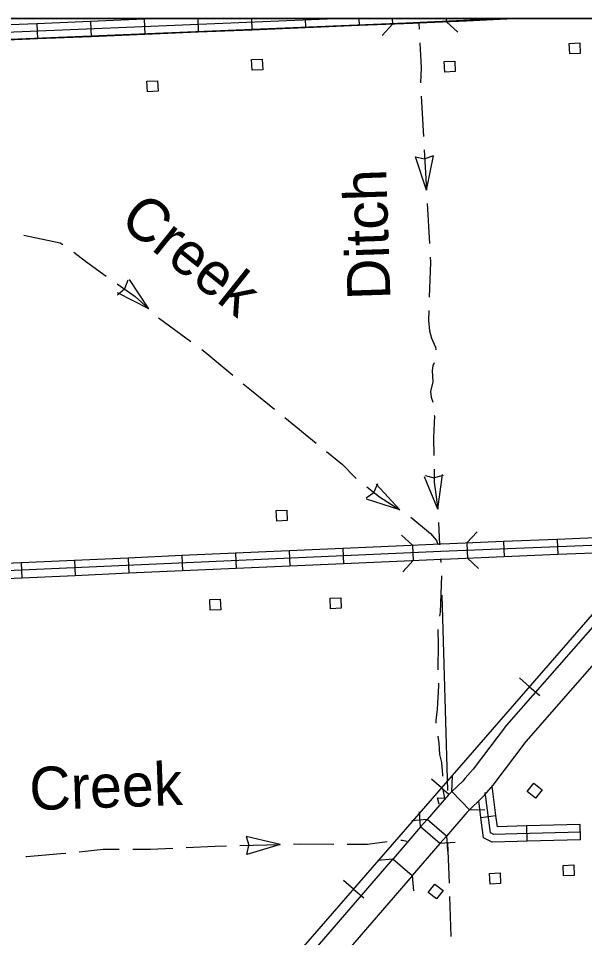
# Model space of a CAD drawing. Extents: x -0.3 to 2.65, y 0 to 1.9.
# Drawn here: x 0.579 to 0.6457, y 0.4334 to 0.5417 of the extents above; entities that cross this region are included whole.
import ezdxf

# ---------------------------------------------------------------- set-up
doc = ezdxf.new("R2010")
doc.units = 0
for name, color, linetype in [('DSN_DRFT_DNC', 7, 'Continuous'), ('Level 12', 7, 'Continuous'), ('Level 15', 7, 'Continuous'), ('Level 19', 7, 'Continuous'), ('Level 20', 7, 'Continuous'), ('Level 27', 7, 'Continuous'), ('Level 28', 7, 'Continuous'), ('Level 29', 7, 'Continuous'), ('Level 30', 7, 'Continuous'), ('Level 6', 7, 'Continuous')]:
    doc.layers.add(name, color=color, linetype=linetype)

msp = doc.modelspace()

# ---------------------------------------------------------------- linework, layer by layer
at = {"layer": 'DSN_DRFT_DNC'}
msp.add_lwpolyline([(0.38477, 0.54167), (1.0319, 0.54167), (1.0319, 0.1443), (0.38477, 0.1443)], close=True, dxfattribs=at)
at = {"layer": 'Level 12'}
for p, q in [((0.62576, 0.52535), (0.62683, 0.52513)), ((0.62704, 0.52145), (0.62576, 0.52535)), ((0.62788, 0.52547), (0.62684, 0.52513)), ((0.62704, 0.52145), (0.62788, 0.52547)), ((0.59188, 0.51083), (0.5915, 0.50981)), ((0.59434, 0.50747), (0.5921, 0.51092)), ((0.59065, 0.5091), (0.59149, 0.5098)), ((0.59434, 0.50747), (0.59068, 0.50934)), ((0.62837, 0.48389), (0.62681, 0.48769)), ((0.62691, 0.48784), (0.62796, 0.48755)), ((0.62903, 0.48783), (0.62797, 0.48755)), ((0.62837, 0.48389), (0.62892, 0.48796)), ((0.62128, 0.48687), (0.62085, 0.48586)), ((0.6239, 0.48381), (0.62112, 0.48683)), ((0.61996, 0.4852), (0.62084, 0.48585)), ((0.6239, 0.48381), (0.61998, 0.48504)), ((0.62833, 0.44989), (0.62917, 0.44983)), ((0.62855, 0.44914), (0.62833, 0.44987)), ((0.60583, 0.44534), (0.60614, 0.44429)), ((0.60982, 0.44439), (0.60583, 0.44534)), ((0.60982, 0.44439), (0.60589, 0.44322)), ((0.60589, 0.44322), (0.60614, 0.44428))]:
    msp.add_line(p, q, dxfattribs=at)
for points in [[(0.62614, 0.54109), (0.62617, 0.54038)], [(0.62626, 0.5388), (0.62642, 0.53586), (0.62635, 0.53407)], [(0.62643, 0.53249), (0.62669, 0.52776)], [(0.62678, 0.52618), (0.62704, 0.52145)], [(0.62713, 0.51987), (0.62739, 0.51514)], [(0.57965, 0.51615), (0.58392, 0.51522), (0.58423, 0.51503)], [(0.58554, 0.51415), (0.5869, 0.51308), (0.58935, 0.51133)], [(0.62748, 0.51356), (0.62751, 0.51295), (0.62738, 0.50883)], [(0.59063, 0.51041), (0.59273, 0.50892), (0.59434, 0.50747)], [(0.62733, 0.50725), (0.6273, 0.50613), (0.62739, 0.50489), (0.62765, 0.50401), (0.62811, 0.50296), (0.62814, 0.50265)], [(0.59551, 0.50641), (0.59561, 0.50632), (0.59932, 0.5036)], [(0.6006, 0.50266), (0.60094, 0.50241), (0.60426, 0.49965)], [(0.62797, 0.50111), (0.62781, 0.50077), (0.6277, 0.50019), (0.62778, 0.49886), (0.62752, 0.49772), (0.62761, 0.49708), (0.62778, 0.49648)], [(0.60547, 0.49865), (0.60643, 0.49785), (0.60914, 0.49564)], [(0.62797, 0.49492), (0.62798, 0.49486), (0.62787, 0.49226), (0.62793, 0.49018)], [(0.61036, 0.49465), (0.61404, 0.49166)], [(0.61526, 0.49066), (0.61716, 0.48912), (0.6186, 0.48763), (0.61878, 0.48749)], [(0.62797, 0.4886), (0.62796, 0.48704), (0.62837, 0.48389)], [(0.62002, 0.48651), (0.6215, 0.48533), (0.6239, 0.48381)], [(0.6252, 0.48292), (0.62752, 0.48102), (0.62823, 0.48017), (0.6284, 0.47973)], [(0.62848, 0.48232), (0.62858, 0.47969)], [(0.62868, 0.47801), (0.62872, 0.47759)], [(0.62881, 0.47601), (0.62864, 0.47175), (0.62859, 0.47128)], [(0.6284, 0.46971), (0.62837, 0.46946), (0.62842, 0.4681), (0.6284, 0.46497)], [(0.62846, 0.4634), (0.62847, 0.46305), (0.62829, 0.46034), (0.62814, 0.459), (0.62813, 0.45867)], [(0.62839, 0.45713), (0.62852, 0.45631), (0.62859, 0.455), (0.62881, 0.45404), (0.62895, 0.45258), (0.62895, 0.45244)], [(0.62898, 0.45087), (0.62918, 0.44981)], [(0.58616, 0.44354), (0.589, 0.44382), (0.59088, 0.44382)], [(0.59246, 0.44382), (0.59457, 0.44382), (0.5972, 0.44394)], [(0.59877, 0.44402), (0.60218, 0.44418), (0.60351, 0.44421)], [(0.60509, 0.44426), (0.60982, 0.44439)], [(0.6114, 0.44443), (0.61213, 0.44445), (0.61614, 0.44443)], [(0.61772, 0.44442), (0.62011, 0.44441), (0.62243, 0.44475)], [(0.62401, 0.44488), (0.62422, 0.44488), (0.62472, 0.44476)], [(0.62953, 0.44459), (0.6297, 0.43985)], [(0.57986, 0.44299), (0.57998, 0.44299), (0.58396, 0.44331), (0.58459, 0.44338)], [(0.62976, 0.43828), (0.62993, 0.43354)]]:
    msp.add_lwpolyline(points, dxfattribs=at)
at = {"layer": 'Level 15'}
for p, q in [((0.58748, 0.5413), (0.58756, 0.53951)), ((0.59582, 0.54164), (0.5938, 0.54156)), ((0.5938, 0.54156), (0.59387, 0.53977)), ((0.60012, 0.54164), (0.60018, 0.54003)), ((0.60644, 0.54164), (0.6065, 0.54029)), ((0.61276, 0.54164), (0.61281, 0.54055)), ((0.61909, 0.54164), (0.61912, 0.54081)), ((0.62302, 0.54164), (0.62305, 0.54097)), ((0.62937, 0.54164), (0.62939, 0.54123)), ((0.63222, 0.54164), (0.63223, 0.54138)), ((0.63811, 0.54164), (0.63806, 0.54164)), ((0.63806, 0.54164), (0.63806, 0.54164)), ((0.58117, 0.54104), (0.58125, 0.53925)), ((0.62541, 0.47961), (0.62548, 0.47782)), ((0.63179, 0.47987), (0.63186, 0.47808)), ((0.63612, 0.48005), (0.63619, 0.47826)), ((0.64243, 0.48031), (0.64251, 0.47852)), ((0.60456, 0.47868), (0.60464, 0.47688)), ((0.61087, 0.47896), (0.61095, 0.47716)), ((0.61718, 0.47924), (0.61726, 0.47744)), ((0.57931, 0.47755), (0.57939, 0.47576)), ((0.58562, 0.47784), (0.5857, 0.47604)), ((0.59193, 0.47812), (0.59201, 0.47632)), ((0.59825, 0.4784), (0.59832, 0.4766)), ((0.63345, 0.44757), (0.63523, 0.4478)), ((0.63892, 0.44478), (0.63888, 0.44658)), ((0.6452, 0.44495), (0.64516, 0.44674))]:
    msp.add_line(p, q, dxfattribs=at)
for points in [[(0.63649, 0.54164), (0.62462, 0.5411), (0.56089, 0.53848), (0.51348, 0.53639), (0.49209, 0.5356)], [(0.61723, 0.54164), (0.56237, 0.53938), (0.51495, 0.5373), (0.49357, 0.53651)], [(0.58748, 0.5413), (0.58117, 0.54104)], [(0.5938, 0.54156), (0.58748, 0.5413)], [(0.63175, 0.54135), (0.62614, 0.5411), (0.62544, 0.54107)], [(0.63806, 0.54164), (0.63175, 0.54135)], [(0.58117, 0.54104), (0.57486, 0.54078)], [(0.6065, 0.54029), (0.60018, 0.54003)], [(0.61281, 0.54055), (0.6065, 0.54029)], [(0.61912, 0.54081), (0.61281, 0.54055)], [(0.62544, 0.54107), (0.61912, 0.54081)], [(0.58125, 0.53925), (0.57493, 0.53899)], [(0.58756, 0.53951), (0.58125, 0.53925)], [(0.59387, 0.53977), (0.58756, 0.53951)], [(0.60018, 0.54003), (0.59387, 0.53977)], [(0.65507, 0.47962), (0.65429, 0.47984), (0.65142, 0.4798), (0.62875, 0.47887), (0.56702, 0.47613), (0.56558, 0.47592), (0.56498, 0.47581), (0.56493, 0.47458), (0.56546, 0.45822), (0.56606, 0.43494), (0.56734, 0.41056)], [(0.62981, 0.47979), (0.62871, 0.47975), (0.62349, 0.47952)], [(0.63612, 0.48005), (0.62981, 0.47979)], [(0.64243, 0.48031), (0.63612, 0.48005)], [(0.64875, 0.48057), (0.64243, 0.48031)], [(0.60456, 0.47868), (0.59825, 0.4784)], [(0.61087, 0.47896), (0.60456, 0.47868)], [(0.61718, 0.47924), (0.61087, 0.47896)], [(0.62349, 0.47952), (0.61718, 0.47924)], [(0.64251, 0.47852), (0.63619, 0.47826)], [(0.64882, 0.47878), (0.64251, 0.47852)], [(0.57931, 0.47755), (0.573, 0.47727)], [(0.58562, 0.47784), (0.57931, 0.47755)], [(0.59193, 0.47812), (0.58562, 0.47784)], [(0.59825, 0.4784), (0.59193, 0.47812)], [(0.61726, 0.47744), (0.61095, 0.47716)], [(0.62357, 0.47772), (0.61726, 0.47744)], [(0.62988, 0.478), (0.62879, 0.47796), (0.62357, 0.47772)], [(0.63619, 0.47826), (0.62988, 0.478)], [(0.59201, 0.47632), (0.5857, 0.47604)], [(0.59832, 0.4766), (0.59201, 0.47632)], [(0.60464, 0.47688), (0.59832, 0.4766)], [(0.61095, 0.47716), (0.60464, 0.47688)], [(0.57939, 0.47576), (0.57308, 0.47548)], [(0.5857, 0.47604), (0.57939, 0.47576)], [(0.6377, 0.44563), (0.63496, 0.44556), (0.63458, 0.44575), (0.63396, 0.45049)], [(0.63523, 0.4478), (0.63478, 0.45124)], [(0.63345, 0.44757), (0.6332, 0.44951)], [(0.63892, 0.44478), (0.63773, 0.44475), (0.63477, 0.44467), (0.63377, 0.44516), (0.63345, 0.44757)], [(0.63888, 0.44658), (0.63768, 0.44654), (0.63541, 0.44648), (0.63523, 0.4478)], [(0.64516, 0.44674), (0.63888, 0.44658)], [(0.64522, 0.44583), (0.6377, 0.44563)], [(0.6452, 0.44495), (0.63892, 0.44478)]]:
    msp.add_lwpolyline(points, dxfattribs=at)
at = {"layer": 'Level 19'}
for points in [[(0.64392, 0.53748), (0.64386, 0.53872), (0.64511, 0.53878), (0.64516, 0.53753)], [(0.60651, 0.53556), (0.60645, 0.53681), (0.6077, 0.53686), (0.60776, 0.53562)], [(0.62919, 0.53534), (0.62913, 0.53658), (0.63038, 0.53664), (0.63044, 0.5354)], [(0.5942, 0.53303), (0.59414, 0.53427), (0.59539, 0.53433), (0.59545, 0.53308)], [(0.60941, 0.48247), (0.60935, 0.48371), (0.6106, 0.48377), (0.61065, 0.48253)], [(0.60157, 0.47197), (0.60152, 0.47322), (0.60276, 0.47327), (0.60282, 0.47203)], [(0.61576, 0.47215), (0.6157, 0.47339), (0.61695, 0.47345), (0.61701, 0.4722)], [(0.6399, 0.44984), (0.63892, 0.45062), (0.6397, 0.4516), (0.64068, 0.45082)], [(0.64318, 0.44068), (0.64313, 0.44193), (0.64438, 0.44198), (0.64443, 0.44074)], [(0.63453, 0.43973), (0.63448, 0.44098), (0.63573, 0.44103), (0.63578, 0.43979)], [(0.62823, 0.43797), (0.62725, 0.43875), (0.62803, 0.43973), (0.629, 0.43895)]]:
    msp.add_lwpolyline(points, close=True, dxfattribs=at)
at = {"layer": 'Level 20'}
msp.add_lwpolyline([(0.62955, 0.45076), (0.6289, 0.47376)], dxfattribs=at)
at = {"layer": 'Level 27'}
msp.add_line((0.63005, 0.45064), (0.63211, 0.44847), dxfattribs=at)
for points in [[(0.69004, 0.51876), (0.65507, 0.47962), (0.63646, 0.45842), (0.63256, 0.45327), (0.63162, 0.45219)], [(0.63387, 0.45021), (0.63489, 0.45138), (0.63878, 0.45652), (0.65732, 0.47766), (0.69025, 0.51451)], [(0.63162, 0.45219), (0.63133, 0.45186), (0.63005, 0.45064)], [(0.63005, 0.45064), (0.62962, 0.45023), (0.62713, 0.44734)], [(0.63211, 0.44847), (0.63349, 0.44979), (0.63387, 0.45021)], [(0.63211, 0.44847), (0.63179, 0.44817), (0.62939, 0.44538)], [(0.62635, 0.44645), (0.62713, 0.44734)], [(0.62713, 0.44735), (0.6294, 0.44539)], [(0.62635, 0.44645), (0.62311, 0.44268)], [(0.62862, 0.4445), (0.62636, 0.44645)], [(0.62939, 0.44538), (0.62862, 0.44449)], [(0.62862, 0.44449), (0.62536, 0.44072)], [(0.53986, 0.34704), (0.59663, 0.412), (0.62311, 0.44268)], [(0.6231, 0.44268), (0.62537, 0.44073)], [(0.62536, 0.44071), (0.59889, 0.41004), (0.54211, 0.34507)]]:
    msp.add_lwpolyline(points, dxfattribs=at)
at = {"layer": 'Level 28'}
for p, q in [((0.63919, 0.46297), (0.638, 0.464)), ((0.63919, 0.46297), (0.64038, 0.46193)), ((0.62883, 0.45105), (0.62763, 0.45208)), ((0.62883, 0.45105), (0.62966, 0.45032)), ((0.61846, 0.43912), (0.61727, 0.44016)), ((0.61846, 0.43912), (0.61966, 0.43809))]:
    msp.add_line(p, q, dxfattribs=at)
for points in [[(0.50451, 0.30855), (0.53786, 0.34671), (0.60158, 0.41969), (0.64921, 0.4745), (0.6908, 0.52224), (0.7076, 0.54164)], [(0.50451, 0.30855), (0.53786, 0.34671), (0.60158, 0.41969), (0.64921, 0.4745), (0.6908, 0.52224), (0.7076, 0.54164)], [(0.50451, 0.30855), (0.53786, 0.34671), (0.60158, 0.41969), (0.64921, 0.4745), (0.6908, 0.52224), (0.7076, 0.54164)], [(0.50451, 0.30855), (0.53786, 0.34671), (0.60158, 0.41969), (0.64921, 0.4745), (0.6908, 0.52224), (0.7076, 0.54164)], [(0.40386, 0.14427), (0.4188, 0.17053), (0.43403, 0.19722), (0.4497, 0.22484), (0.4732, 0.266), (0.47682, 0.27303), (0.47817, 0.27549), (0.4797, 0.2782), (0.48111, 0.28039), (0.48332, 0.28357), (0.48511, 0.28592), (0.48761, 0.28907), (0.49328, 0.29577), (0.49996, 0.30333), (0.50451, 0.30855), (0.53786, 0.34671), (0.60158, 0.41969), (0.64921, 0.4745), (0.68992, 0.52123)]]:
    msp.add_lwpolyline(points, dxfattribs=at)
at = {"layer": 'Level 29'}
for points in [[(0.63072, 0.54005), (0.62939, 0.54126)], [(0.62305, 0.54099), (0.62183, 0.53967)], [(0.62409, 0.48083), (0.62541, 0.47962)], [(0.6318, 0.47989), (0.63302, 0.48121)], [(0.62549, 0.47783), (0.62428, 0.4765)], [(0.63319, 0.47688), (0.63187, 0.4781)]]:
    msp.add_lwpolyline(points, dxfattribs=at)
at = {"layer": 'Level 30'}
for points in [[(0.63005, 0.45064), (0.6301, 0.45244)], [(0.62636, 0.44645), (0.62622, 0.44824)], [(0.63391, 0.44843), (0.63211, 0.44847)], [(0.62534, 0.44722), (0.62713, 0.44735)], [(0.6294, 0.44539), (0.62953, 0.4436)], [(0.63041, 0.44463), (0.62862, 0.4445)], [(0.62131, 0.44255), (0.6231, 0.44268)], [(0.62537, 0.44073), (0.6255, 0.43894)]]:
    msp.add_lwpolyline(points, dxfattribs=at)
at = {"layer": 'Level 6'}
msp.add_lwpolyline([(1.03189, 0.54164), (1.03189, 0.54164), (0.38476, 0.54164)], dxfattribs=at)

# ---------------------------------------------------------------- texts
at = {"layer": 'Level 12'}
for s, rotation, p in [('Ditch', 91.8911, (0.62281, 0.50859)), ('Creek', 321.5056, (0.59071, 0.51751)), ('Creek', 2.0333, (0.58037, 0.44841))]:
    msp.add_text(s, height=0.005055, rotation=rotation, dxfattribs=at).set_placement(p)

doc.saveas('drawing.dxf')
